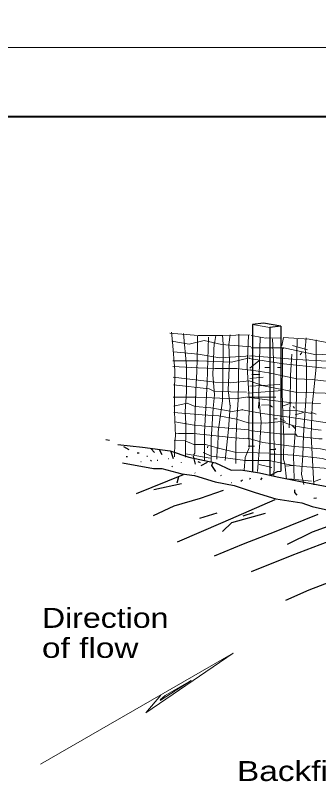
# Model space of a CAD drawing. Extents: x 1083.1 to 1117.1, y 672.5 to 716.5.
# Drawn here: x 1106.01 to 1108.38, y 688.7 to 694.76 of the extents above; entities that cross this region are included whole.
import ezdxf
from ezdxf.enums import TextEntityAlignment as Align

# ---------------------------------------------------------------- set-up
doc = ezdxf.new("R2010")
doc.units = 0
doc.header["$LTSCALE"] = 0.062
doc.linetypes.add('LONG_DASHED', pattern=[7.5, 6, -1.5])
doc.layers.add('1', color=7, linetype='Continuous', lineweight=13)

msp = doc.modelspace()

# ---------------------------------------------------------------- linework, layer by layer
at = {"layer": '1', "lineweight": 25}
for p, q in [((1085.14617, 693.96842), (1116.64617, 693.96842)), ((1107.94825, 692.35158), (1107.86283, 692.34067)), ((1107.86283, 692.34067), (1107.86283, 691.19217)), ((1108.08358, 692.32925), (1107.94825, 692.35158)), ((1108.08358, 692.32925), (1107.99817, 692.31833)), ((1108.08358, 692.32925), (1108.08358, 691.19442)), ((1107.99817, 692.31833), (1107.99817, 691.16167)), ((1106.71625, 691.44233), (1106.74583, 691.43658)), ((1106.89925, 691.362), (1106.85892, 691.38492)), ((1107.09842, 691.339), (1107.06883, 691.37058)), ((1107.15767, 691.32175), (1107.13608, 691.362)), ((1106.87508, 691.30775), (1106.88583, 691.30775)), ((1106.96117, 691.3365), (1106.97733, 691.3365)), ((1107.03658, 691.31067), (1107.04192, 691.31067)), ((1107.20617, 691.29342), (1107.20883, 691.29342)), ((1107.2465, 691.29017), (1107.22767, 691.34475)), ((1107.41875, 691.25), (1107.40258, 691.31033)), ((1106.99083, 691.2705), (1106.9935, 691.2705)), ((1107.06617, 691.27908), (1107.07425, 691.27333)), ((1107.11733, 691.27908), (1107.12267, 691.27908)), ((1107.233, 691.22742), (1107.23842, 691.23317)), ((1107.30575, 691.26475), (1107.30575, 691.26183)), ((1107.45642, 691.25867), (1107.43758, 691.26725)), ((1107.46183, 691.2385), (1107.51025, 691.26433)), ((1107.41342, 691.1815), (1107.41608, 691.17867)), ((1106.95583, 691.02075), (1107.32458, 691.16717)), ((1107.27342, 691.10367), (1107.28683, 691.15242)), ((1107.61525, 691.16142), (1107.62067, 691.16425)), ((1107.77133, 691.1155), (1107.78483, 691.127)), ((1107.9275, 691.127), (1107.93825, 691.14133)), ((1107.30842, 691.09542), (1107.09308, 691.0495)), ((1107.69867, 691.10683), (1107.70142, 691.10683)), ((1108.24775, 690.94617), (1108.32833, 690.91767)), ((1108.342, 690.98342), (1108.3635, 690.98633)), ((1107.45108, 690.82558), (1107.58567, 690.86867)), ((1107.86825, 690.86825), (1107.7875, 690.84242)), ((1108.12317, 690.18608), (1108.30483, 690.26558))]:
    msp.add_line(p, q, dxfattribs=at)
at = {"layer": '1'}
for p, q in [((1107.99817, 692.31833), (1107.86283, 692.34067)), ((1107.87317, 692.34042), (1107.86633, 692.34042)), ((1107.75517, 692.24883), (1107.75508, 692.26583)), ((1107.63408, 692.18858), (1107.62783, 692.25733)), ((1107.67717, 692.18567), (1107.68808, 692.25942)), ((1107.96783, 692.2345), (1107.85208, 692.25458)), ((1108.08083, 692.2345), (1107.9705, 692.23733)), ((1108.27467, 692.15417), (1108.28008, 692.20583)), ((1107.63133, 691.89867), (1107.63408, 692.18858)), ((1108.10775, 692.15983), (1108.36083, 692.10533)), ((1108.2935, 692.14267), (1108.17508, 692.17708)), ((1108.28542, 692.02783), (1108.27467, 692.15417)), ((1107.60717, 692.0795), (1107.85208, 692.09675)), ((1107.85208, 692.09675), (1108.21008, 692.068)), ((1108.24775, 692.12258), (1108.23425, 692.10533)), ((1107.84133, 691.99917), (1107.91133, 692.05658)), ((1108.49267, 692.05083), (1108.21008, 692.068)), ((1107.95975, 692.00492), (1107.99742, 692.00492)), ((1108.05933, 692.00492), (1108.08625, 692.00492)), ((1107.62867, 691.74367), (1107.63133, 691.89867)), ((1107.84133, 691.91875), (1107.94625, 691.93025)), ((1107.8575, 691.95033), (1107.91933, 691.95033)), ((1107.2465, 691.87), (1107.52375, 691.83842)), ((1107.52375, 691.83842), (1107.56675, 691.81833)), ((1107.84133, 691.8585), (1108.0755, 691.87283)), ((1107.56675, 691.7925), (1107.556, 691.68625)), ((1107.81708, 691.81258), (1107.56675, 691.81833)), ((1107.82517, 691.804), (1108.097, 691.82408)), ((1107.24333, 691.77242), (1107.42683, 691.77242)), ((1107.24917, 691.7035), (1107.35142, 691.7265)), ((1107.35142, 691.7265), (1107.41608, 691.70067)), ((1107.42683, 691.77242), (1107.72825, 691.76092)), ((1107.81175, 691.77242), (1107.72825, 691.76092)), ((1107.74983, 691.75233), (1107.74175, 691.59733)), ((1107.81708, 691.77242), (1108.04592, 691.77242)), ((1107.91133, 691.73508), (1107.90858, 691.68625)), ((1108.16967, 691.72933), (1108.10242, 691.70642)), ((1108.15625, 691.72933), (1108.14808, 691.53208)), ((1108.33117, 691.7265), (1108.16967, 691.72933)), ((1108.33117, 691.7265), (1108.39308, 691.72358)), ((1107.25458, 691.65758), (1107.26267, 691.471)), ((1107.67442, 691.52267), (1107.68792, 691.70067)), ((1107.94092, 691.64608), (1107.78208, 691.67483)), ((1107.98933, 691.71208), (1107.93283, 691.70925)), ((1108.019, 691.69492), (1107.99475, 691.71208)), ((1108.20467, 691.66908), (1108.10017, 691.671)), ((1108.18042, 691.70067), (1108.19125, 691.68625)), ((1108.32308, 691.64608), (1108.20467, 691.66908)), ((1108.36083, 691.64033), (1108.31775, 691.65475)), ((1107.73367, 691.39925), (1107.74175, 691.59733)), ((1107.739, 691.60017), (1107.82783, 691.5715)), ((1108.03508, 691.60308), (1108.05667, 691.60308)), ((1108.12125, 691.583), (1108.07817, 691.60308)), ((1108.19658, 691.63467), (1108.26117, 691.65183)), ((1108.20467, 691.64608), (1108.19933, 691.52558)), ((1107.34333, 691.56575), (1107.34067, 691.30458)), ((1107.83325, 691.51692), (1107.6475, 691.53417)), ((1108.08625, 691.583), (1108.16967, 691.55425)), ((1108.35275, 691.51983), (1108.16967, 691.55142)), ((1107.28417, 691.48825), (1107.26008, 691.4925)), ((1107.67442, 691.52267), (1107.65058, 691.27892)), ((1108.09975, 691.4825), (1107.83058, 691.51125)), ((1108.35275, 691.51983), (1108.3985, 691.51408)), ((1107.72558, 691.45383), (1107.82783, 691.44808)), ((1108.10775, 691.45667), (1108.10508, 691.2845)), ((1108.32042, 691.471), (1108.34175, 691.08658)), ((1107.51025, 691.37633), (1107.51292, 691.39067)), ((1107.58558, 691.37633), (1107.58375, 691.28858)), ((1107.58558, 691.37633), (1107.72558, 691.34183)), ((1107.73367, 691.39925), (1107.73275, 691.25325)), ((1107.82783, 691.39067), (1107.879, 691.39067)), ((1107.99475, 691.36483), (1108.04317, 691.36483)), ((1108.04317, 691.36483), (1108.04325, 691.37183)), ((1107.53175, 691.29592), (1107.34067, 691.33042)), ((1107.72558, 691.34183), (1107.98933, 691.33617)), ((1108.18317, 691.31892), (1108.04858, 691.3275)), ((1108.18317, 691.31892), (1108.18908, 691.1325)), ((1107.80092, 691.27875), (1107.99208, 691.27875)), ((1107.914, 691.24717), (1108.01358, 691.22417)), ((1107.99208, 691.27875), (1108.17775, 691.2385)), ((1108.11583, 691.25292), (1108.10508, 691.2845)), ((1108.12717, 691.13192), (1108.11583, 691.25292)), ((1108.32308, 691.11508), (1108.1455, 691.13525)), ((1108.26283, 691.09033), (1108.24508, 691.16967)), ((1108.34467, 691.11225), (1108.39575, 691.13233))]:
    msp.add_line(p, q, dxfattribs=at)
at = {"layer": '1', "linetype": 'LONG_DASHED'}
for points in [[(1083.12642, 694.50825), (1117.12642, 694.50825), (1117.12642, 716.50825), (1083.12642, 716.50825)], [(1083.12642, 672.50825), (1117.12642, 672.50825), (1117.12642, 694.50825), (1083.12642, 694.50825)]]:
    msp.add_lwpolyline(points, close=True, dxfattribs=at)
at = {"layer": '1', "lineweight": 40}
msp.add_lwpolyline([(1085.14617, 693.96842), (1116.64617, 693.96842), (1116.64617, 672.96842), (1085.14617, 672.96842)], close=True, dxfattribs=at)
at = {"layer": '1'}
for points in [[(1107.21683, 692.27467), (1107.43758, 692.25458), (1107.626, 692.25458), (1107.83867, 692.26033)], [(1107.25458, 691.65758), (1107.25458, 691.7925), (1107.25725, 691.98192), (1107.23842, 692.20583), (1107.23033, 692.28042)], [(1107.338, 691.6605), (1107.34608, 691.81542), (1107.34608, 692.01633), (1107.3245, 692.27183)], [(1107.84942, 692.16558), (1107.62058, 692.18567), (1107.486, 692.21725), (1107.36758, 692.18858), (1107.233, 692.2115)], [(1107.40258, 691.31892), (1107.41333, 691.33617), (1107.41333, 691.51408), (1107.41608, 691.65475), (1107.42142, 691.82408), (1107.42683, 691.97333), (1107.43217, 692.18), (1107.43217, 692.24883)], [(1107.48875, 691.27875), (1107.48875, 691.50258), (1107.4995, 691.68625), (1107.50758, 691.88717), (1107.51833, 692.24308)], [(1107.56408, 692.19433), (1107.56542, 692.19233), (1107.57558, 692.25625)], [(1107.75517, 692.24883), (1107.75517, 692.10533), (1107.7525, 691.89583), (1107.74983, 691.75233)], [(1107.83117, 692.25617), (1107.82217, 692.01008), (1107.83783, 691.75775), (1107.83342, 691.50333), (1107.83783, 691.38142)], [(1107.92308, 692.23933), (1107.91633, 692.06475), (1107.91183, 691.77458), (1107.92983, 691.577), (1107.92083, 691.41508), (1107.90292, 691.19217)], [(1108.0195, 692.22883), (1108.02842, 692.0185), (1108.02842, 691.741), (1108.02842, 691.47392), (1108.03517, 691.312), (1108.02842, 691.1585)], [(1108.09167, 692.17425), (1108.10508, 692.24025), (1108.30425, 692.22592), (1108.47117, 692.19433), (1108.69458, 692.19717), (1108.77533, 692.18567), (1108.92067, 692.1685)], [(1108.20467, 691.64608), (1108.20733, 691.82983), (1108.20733, 692.00492), (1108.21275, 692.22592)], [(1108.28008, 692.20583), (1108.279, 692.2085), (1108.28233, 692.23833)], [(1108.36083, 692.22017), (1108.36083, 692.00775), (1108.3285, 691.70642), (1108.32042, 691.471)], [(1107.56675, 691.7925), (1107.55333, 691.95033), (1107.56408, 692.19433)], [(1107.67175, 691.82983), (1107.6825, 692.05658), (1107.67717, 692.18567)], [(1108.10775, 691.45667), (1108.09975, 691.64608), (1108.09433, 691.80683), (1108.097, 692.04217), (1108.097, 692.15125), (1108.10775, 692.15983), (1107.85208, 692.15983)], [(1108.94758, 692.12258), (1108.708, 692.14842), (1108.56808, 692.11392), (1108.36083, 692.10533)], [(1107.83867, 692.0795), (1107.69867, 692.04792), (1107.44025, 692.05658), (1107.24108, 692.05658)], [(1107.2465, 692.12833), (1107.43758, 692.10825), (1107.60717, 692.0795)], [(1108.15625, 691.72933), (1108.15892, 691.94458), (1108.16967, 692.10825)], [(1108.66492, 691.98483), (1108.40383, 692.002), (1108.10508, 692.03358), (1107.83592, 692.07667)], [(1108.24508, 691.16967), (1108.25583, 691.31317), (1108.26117, 691.47675), (1108.28542, 691.82408), (1108.28542, 692.02783)], [(1107.84667, 691.98483), (1107.74175, 691.99625), (1107.57217, 691.99625), (1107.43758, 692.002), (1107.24108, 692.0135)], [(1108.21008, 691.91592), (1107.99083, 691.96375), (1107.85408, 691.98517), (1107.84667, 691.98483), (1107.8495, 691.98942)], [(1107.83592, 691.90158), (1107.69325, 691.88433), (1107.5695, 691.89008), (1107.24375, 691.93025)], [(1108.19933, 691.81258), (1107.94983, 691.86117), (1107.83592, 691.90158)], [(1108.21008, 691.91592), (1108.3285, 691.91017), (1108.48458, 691.89292), (1108.59767, 691.84992), (1108.66767, 691.87283), (1108.76183, 691.84417)], [(1107.67175, 691.82983), (1107.68792, 691.70067), (1107.68992, 691.71092)], [(1108.68917, 691.79825), (1108.54917, 691.7925), (1108.43075, 691.804), (1108.19933, 691.81258)], [(1107.591, 691.37058), (1107.59367, 691.50258), (1107.6125, 691.63467), (1107.62867, 691.74367)], [(1108.16967, 691.72933), (1108.04317, 691.74367), (1107.81708, 691.77242)], [(1107.338, 691.6605), (1107.34333, 691.56575), (1107.33892, 691.57117)], [(1107.70408, 691.6605), (1107.53717, 691.68917), (1107.41608, 691.70067)], [(1107.53983, 691.27008), (1107.53983, 691.44233), (1107.556, 691.68625)], [(1107.70408, 691.6605), (1107.78208, 691.67483), (1107.78242, 691.67875)], [(1107.739, 691.60017), (1107.59908, 691.626), (1107.46992, 691.63467), (1107.24917, 691.65183)], [(1108.46308, 691.56858), (1108.14808, 691.61542), (1107.94092, 691.64608)], [(1107.6475, 691.53417), (1107.40742, 691.5535), (1107.25667, 691.57925)], [(1108.08625, 691.583), (1107.96117, 691.56858), (1107.82783, 691.5715)], [(1108.16967, 691.55425), (1108.19933, 691.52558), (1108.18317, 691.31892), (1108.40925, 691.29308), (1108.46575, 691.27583)], [(1107.72558, 691.45383), (1107.58025, 691.471), (1107.40258, 691.48825), (1107.28417, 691.48825)], [(1108.09975, 691.4825), (1108.202, 691.4825), (1108.21275, 691.46817), (1108.26925, 691.45958), (1108.37967, 691.44808), (1108.40658, 691.44808)], [(1107.25183, 691.43658), (1107.338, 691.43083), (1107.40525, 691.40217), (1107.49683, 691.40217), (1107.58558, 691.37633)], [(1107.25458, 691.30742), (1107.25725, 691.42225), (1107.26267, 691.471)], [(1108.167, 691.39067), (1107.94325, 691.41717), (1107.82667, 691.45292)], [(1107.83592, 691.37633), (1107.80633, 691.30167), (1107.79825, 691.20125)], [(1108.46575, 691.35333), (1108.39308, 691.36767), (1108.167, 691.39067)], [(1107.80633, 691.27875), (1107.66908, 691.29592), (1107.54258, 691.31033), (1107.47792, 691.339)], [(1108.00008, 691.21842), (1107.99742, 691.3275), (1108.04858, 691.3275)], [(1108.12125, 691.23283), (1108.17775, 691.2385), (1108.28808, 691.22708), (1108.42267, 691.21842), (1108.58958, 691.21267)], [(1106.208, 688.90333), (1107.7115, 689.77142), (1107.02975, 689.30542), (1107.148, 689.44308)], [(1107.14125, 689.40008), (1107.38258, 689.55742), (1107.18067, 689.44083), (1107.14292, 689.40708)]]:
    msp.add_lwpolyline(points, dxfattribs=at)
at = {"layer": '1', "lineweight": 25}
for points in [[(1106.81042, 691.40217), (1107.00425, 691.38208), (1107.21958, 691.35333), (1107.36492, 691.30458), (1107.57483, 691.25867), (1107.696, 691.20125), (1107.77133, 691.20408), (1107.91667, 691.18117), (1108.05667, 691.14958), (1108.237, 691.11225), (1108.47117, 691.06917), (1108.58692, 691.04625), (1108.70533, 691.01175), (1108.85333, 690.98883)], [(1106.84817, 691.259), (1107.09042, 691.21592), (1107.155, 691.21592), (1107.31108, 691.17292), (1107.41067, 691.16142), (1107.57217, 691.10975), (1107.72025, 691.081), (1107.88442, 691.0265), (1108.04592, 690.97775), (1108.24775, 690.94617)], [(1107.5775, 691.19258), (1107.54525, 691.2385), (1107.556, 691.26725)], [(1107.99817, 691.16167), (1108.05908, 691.19167), (1108.08358, 691.19442)], [(1107.844, 691.13842), (1107.84133, 691.13267), (1107.83867, 691.13267)], [(1108.21275, 691.00642), (1108.19392, 691.0265), (1108.19392, 691.0495)], [(1107.09042, 690.84858), (1107.25192, 690.92317), (1107.45642, 690.98342), (1107.63675, 691.04658)], [(1108.03783, 690.96908), (1107.63142, 690.794), (1107.27342, 690.639)], [(1108.32833, 690.91767), (1108.74933, 690.82483), (1108.79633, 690.79725), (1108.82225, 690.81233), (1109.00808, 690.77717), (1109.13742, 690.75467), (1109.295, 690.707), (1109.469, 690.65683), (1109.57017, 690.62425)], [(1107.56683, 690.53283), (1107.79292, 690.62467), (1108.04858, 690.72517), (1108.377, 690.85717)], [(1107.62867, 690.72225), (1107.70142, 690.794), (1107.96517, 690.86575)], [(1107.85558, 690.4085), (1108.17308, 690.53642), (1108.39183, 690.62167), (1108.57767, 690.69192), (1108.72583, 690.75717), (1108.80108, 690.80225)], [(1108.13542, 690.62425), (1108.33067, 690.7195), (1108.453, 690.76467), (1108.54942, 690.80225)], [(1108.30483, 690.26558), (1108.57058, 690.36842), (1108.68583, 690.36333), (1108.83167, 690.401), (1109.56075, 690.63425)]]:
    msp.add_lwpolyline(points, dxfattribs=at)

# ---------------------------------------------------------------- texts
at = {"layer": '1'}
for s, width, p in [('Direction', 1.2, (1106.2185, 689.96883)), ('of flow', 1.25, (1106.2185, 689.73417))]:
    msp.add_text(s, height=0.156, dxfattribs=dict(at, width=width)).set_placement(p)
at = {"layer": '1', "width": 1.25}
msp.add_text('Backfill and compact the excavated soil.', height=0.156, dxfattribs=at).set_placement((1110.05363, 688.771), align=Align.CENTER)

doc.saveas('drawing.dxf')
